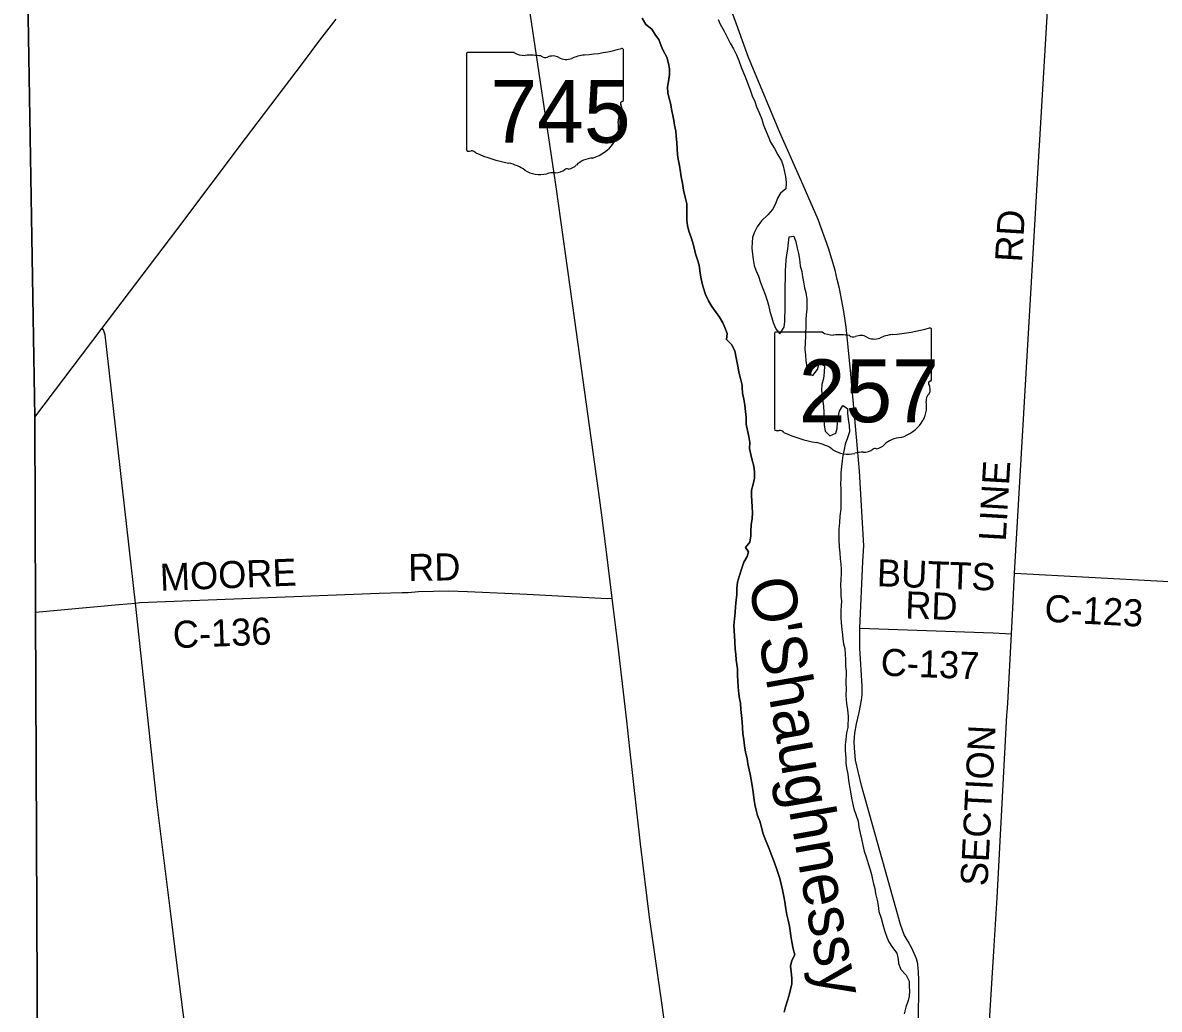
# Model space of a CAD drawing. Extents: x 1674899 to 2057726, y 653888 to 988278.
# Drawn here: x 1780755 to 1793352, y 803604 to 814535 of the extents above; entities that cross this region are included whole.
import ezdxf

# ---------------------------------------------------------------- set-up
doc = ezdxf.new("R2010")
doc.units = 0
for name, color, linetype in [('GM_X_Adjacent_County', 7, 'Continuous'), ('GM_X_County', 7, 'Continuous'), ('GM_X_County_Road', 7, 'Continuous'), ('GM_X_County_Road_Text', 7, 'Continuous'), ('GM_X_Major_Lake', 7, 'Continuous'), ('GM_X_Major_Lake_Text', 7, 'Continuous'), ('GM_X_Major_River', 7, 'Continuous'), ('GM_X_State_Location', 7, 'Continuous'), ('GM_X_State_Route', 7, 'Continuous'), ('GM_X_State_Shield', 7, 'Continuous'), ('GM_X_Township', 7, 'Continuous'), ('GM_X_US_Route', 7, 'Continuous'), ('SH_Data', 7, 'Continuous')]:
    doc.layers.add(name, color=color, linetype=linetype)

msp = doc.modelspace()

# ---------------------------------------------------------------- linework, layer by layer
at = {"layer": 'GM_X_Adjacent_County'}
msp.add_lwpolyline([(1780755, 818148), (1780889, 810163), (1780895, 808002), (1780927, 801312), (1780979, 800357), (1781040, 795733), (1781062, 793102), (1781083, 789921), (1781088, 789265), (1781086, 787507), (1781084, 787075), (1781136, 786470), (1781151, 786236), (1781162, 786094), (1781118, 783904)], dxfattribs=at)
at = {"layer": 'GM_X_County'}
msp.add_lwpolyline([(1781118, 783904), (1781162, 786094), (1781151, 786236), (1781136, 786470), (1781084, 787075), (1781086, 787507), (1781088, 789265), (1781083, 789921), (1781062, 793102), (1781040, 795733), (1780979, 800357), (1780927, 801312), (1780895, 808002), (1780889, 810163), (1780755, 818148)], dxfattribs=at)
at = {"layer": 'GM_X_County_Road'}
for points in [[(1791713, 807764), (1791713, 807764), (1791727, 808049), (1791747, 808435), (1791981, 812422), (1791996, 812680), (1792152, 815352), (1792421, 819851), (1792558, 822011)], [(1782890, 800490), (1782881, 800644), (1782856, 800863), (1782676, 802437), (1782464, 804119), (1782395, 804661), (1782246, 805871), (1782006, 808105), (1781669, 811078), (1781659, 811109), (1781650, 811131), (1781636, 811151)], [(1791747, 808435), (1793395, 808348), (1794980, 808260), (1797031, 808146), (1797107, 808141), (1797153, 808138)], [(1780895, 808002), (1781819, 808088), (1782006, 808105), (1782052, 808109), (1784707, 808216), (1784962, 808220), (1785026, 808223), (1785143, 808231), (1785474, 808240), (1785685, 808234), (1786347, 808204), (1787231, 808155), (1787289, 808159)], [(1790033, 807825), (1791509, 807773), (1791713, 807764)], [(1791328, 800949), (1791359, 801588), (1791381, 801980), (1791400, 802336), (1791517, 804248), (1791555, 804839), (1791576, 805255), (1791663, 806861), (1791666, 806898), (1791673, 806996), (1791713, 807764)]]:
    msp.add_lwpolyline(points, dxfattribs=at)
at = {"layer": 'GM_X_Major_Lake'}
for points in [[(1788122, 812288), (1788116, 812346), (1788114, 812413), (1788117, 812471), (1788117, 812527), (1788097, 812601), (1788080, 812679), (1788066, 812758), (1788052, 812826), (1788044, 812878), (1788035, 812954), (1788021, 813022), (1788013, 813072), (1788009, 813141), (1788006, 813203), (1787998, 813283), (1787992, 813333), (1787980, 813401), (1787971, 813452), (1787959, 813508), (1787951, 813558), (1787935, 813642), (1787921, 813694), (1787904, 813757), (1787900, 813823), (1787914, 813885), (1787925, 813961), (1787925, 814023), (1787913, 814085), (1787893, 814155), (1787854, 814228), (1787832, 814280), (1787804, 814348), (1787770, 814399), (1787726, 814463), (1787662, 814517), (1787620, 814586)], [(1788461, 814570), (1788484, 814520), (1788528, 814443), (1788562, 814375), (1788596, 814309), (1788632, 814244), (1788665, 814178), (1788691, 814116), (1788719, 814043), (1788743, 813979), (1788765, 813927), (1788792, 813857), (1788818, 813790), (1788840, 813724), (1788868, 813664), (1788886, 813602), (1788921, 813529), (1788945, 813467), (1788967, 813401), (1788995, 813329), (1789025, 813260), (1789044, 813210), (1789086, 813140), (1789124, 813073), (1789164, 813003), (1789182, 812951), (1789195, 812897), (1789209, 812830), (1789215, 812764), (1789213, 812696), (1789154, 812646), (1789120, 812590), (1789098, 812528), (1789065, 812464), (1789015, 812406), (1788944, 812339), (1788894, 812275), (1788862, 812207), (1788845, 812155), (1788839, 812104), (1788837, 812038), (1788843, 811972), (1788850, 811912), (1788862, 811846), (1788880, 811794), (1788910, 811727), (1788931, 811657), (1788959, 811591), (1788985, 811523), (1789007, 811456), (1789019, 811404), (1789034, 811334), (1789056, 811266), (1789074, 811213), (1789102, 811143), (1789148, 811087), (1789194, 811161), (1789200, 811223), (1789203, 811273), (1789205, 811339), (1789207, 811409), (1789205, 811471), (1789204, 811526), (1789204, 811590), (1789208, 811726), (1789209, 811790), (1789211, 811840), (1789217, 811908), (1789222, 811960), (1789234, 812031), (1789250, 812163), (1789301, 812169), (1789322, 812106), (1789338, 812038), (1789352, 811978), (1789364, 811916), (1789373, 811843), (1789389, 811777), (1789397, 811721), (1789407, 811663), (1789419, 811599), (1789434, 811544), (1789444, 811472), (1789444, 811362), (1789439, 811300)], [(1788728, 810520), (1788712, 810592), (1788693, 810662), (1788683, 810712), (1788673, 810768), (1788663, 810820), (1788647, 810899), (1788612, 810971), (1788554, 811025), (1788562, 811092), (1788538, 811158), (1788514, 811208), (1788477, 811272), (1788441, 811323), (1788391, 811389), (1788357, 811453), (1788323, 811524), (1788299, 811592), (1788286, 811646), (1788272, 811716), (1788258, 811784), (1788252, 811847), (1788235, 811907), (1788213, 811973), (1788195, 812041), (1788179, 812106), (1788162, 812156), (1788138, 812224), (1788122, 812288)], [(1789439, 811300), (1789435, 811250), (1789433, 811198), (1789432, 811067), (1789428, 810987), (1789424, 810917), (1789429, 810851), (1789435, 810791), (1789441, 810739), (1789453, 810668)], [(1789453, 810668), (1789455, 810652), (1789511, 810626), (1789565, 810692), (1789583, 810764), (1789643, 810734), (1789639, 810662), (1789631, 810591), (1789612, 810527), (1789608, 810459), (1789614, 810407), (1789622, 810339), (1789629, 810287), (1789633, 810215), (1789637, 810150), (1789637, 810080), (1789650, 810008), (1789700, 809956), (1789767, 809988), (1789783, 810038), (1789787, 810106), (1789791, 810166), (1789806, 810232), (1789846, 810294), (1789898, 810260), (1789896, 810209), (1789902, 810141), (1789913, 810073), (1789917, 810003), (1789897, 809935), (1789870, 809865), (1789858, 809807), (1789846, 809739), (1789837, 809681), (1789829, 809616), (1789823, 809548), (1789821, 809482), (1789818, 809428), (1789822, 809362), (1789824, 809300), (1789823, 809200), (1789821, 809147), (1789813, 809067), (1789806, 808997), (1789800, 808925), (1789802, 808875), (1789802, 808809), (1789805, 808725), (1789813, 808662), (1789815, 808596), (1789821, 808534), (1789826, 808482), (1789826, 808426), (1789824, 808374), (1789820, 808304), (1789821, 808235), (1789823, 808181), (1789829, 808131), (1789827, 808075), (1789824, 808023), (1789822, 807941), (1789826, 807889), (1789833, 807812), (1789841, 807754), (1789845, 807704), (1789853, 807652), (1789867, 807602), (1789870, 807534), (1789874, 807482), (1789874, 807409), (1789880, 807347), (1789879, 807213), (1789881, 807159), (1789878, 807079), (1789884, 806993), (1789896, 806920), (1789902, 806850), (1789901, 806726), (1789887, 806666), (1789878, 806594), (1789870, 806532), (1789872, 806469), (1789877, 806387), (1789879, 806331), (1789885, 806279), (1789899, 806209), (1789908, 806141), (1789920, 806072), (1789928, 806014), (1789940, 805944), (1789950, 805892), (1789967, 805824), (1789987, 805762), (1790015, 805689), (1790023, 805621), (1790038, 805553), (1790050, 805493), (1790066, 805420), (1790080, 805356), (1790105, 805292), (1790127, 805220)], [(1789264, 804082), (1789278, 804144), (1789311, 804206), (1789295, 804274), (1789281, 804352), (1789267, 804416), (1789260, 804472), (1789254, 804525), (1789240, 804591), (1789224, 804651), (1789211, 804717), (1789201, 804793), (1789191, 804853), (1789175, 804926), (1789160, 804990), (1789146, 805054), (1789128, 805108), (1789104, 805176), (1789076, 805255), (1789057, 805305), (1789029, 805383), (1789007, 805435), (1788985, 805490), (1788959, 805560), (1788944, 805622), (1788924, 805688), (1788898, 805751), (1788882, 805823), (1788869, 805873), (1788857, 805945), (1788849, 806009), (1788841, 806084), (1788828, 806146), (1788816, 806208), (1788808, 806258), (1788792, 806322), (1788783, 806382), (1788767, 806453), (1788755, 806523), (1788747, 806589), (1788736, 806661), (1788734, 806721), (1788730, 806787), (1788720, 806858), (1788715, 806926), (1788709, 806996), (1788699, 807048), (1788691, 807100), (1788684, 807174), (1788680, 807245), (1788678, 807297), (1788677, 807375), (1788671, 807425), (1788661, 807477), (1788657, 807539), (1788651, 807594), (1788646, 807676), (1788644, 807744), (1788640, 807794), (1788638, 807856), (1788645, 807930), (1788653, 808000), (1788655, 808066), (1788662, 808137), (1788668, 808201), (1788668, 808265), (1788677, 808337), (1788699, 808411), (1788721, 808481), (1788748, 808557), (1788786, 808619), (1788800, 808671), (1788764, 808721), (1788813, 808781), (1788825, 808851), (1788825, 808902), (1788828, 808970), (1788838, 809040), (1788844, 809106), (1788841, 809172), (1788837, 809232), (1788833, 809296), (1788833, 809356), (1788850, 809423), (1788866, 809487), (1788864, 809557), (1788859, 809623), (1788841, 809687), (1788825, 809751), (1788811, 809816), (1788812, 809882), (1788802, 809950), (1788788, 810016), (1788774, 810088), (1788773, 810165), (1788767, 810229), (1788757, 810297), (1788749, 810365), (1788732, 810429), (1788730, 810495), (1788728, 810520)], [(1790127, 805220), (1790149, 805150), (1790161, 805095), (1790172, 805043), (1790184, 804993), (1790198, 804941), (1790206, 804885), (1790226, 804811), (1790235, 804752), (1790245, 804686), (1790269, 804612), (1790289, 804544), (1790306, 804476), (1790332, 804403), (1790354, 804351), (1790396, 804287), (1790442, 804224), (1790457, 804160), (1790463, 804110), (1790489, 804044), (1790547, 803980), (1790579, 803915), (1790578, 803857), (1790582, 803803), (1790580, 803749), (1790568, 803699), (1790543, 803625), (1790525, 803553)], [(1789193, 803573), (1789210, 803629), (1789230, 803701), (1789253, 803773), (1789265, 803823), (1789281, 803885), (1789279, 803947), (1789272, 804018), (1789264, 804082)]]:
    msp.add_lwpolyline(points, dxfattribs=at)
at = {"layer": 'GM_X_Major_River'}
for points in [[(1787620, 814586), (1787662, 814517), (1787726, 814463), (1787770, 814399), (1787804, 814348), (1787832, 814280), (1787854, 814228), (1787893, 814155), (1787913, 814085), (1787925, 814023), (1787925, 813961), (1787914, 813885), (1787900, 813823), (1787904, 813757), (1787921, 813694), (1787935, 813642), (1787951, 813558), (1787959, 813508), (1787971, 813452), (1787980, 813401), (1787992, 813333), (1787998, 813283), (1788006, 813203), (1788009, 813141), (1788013, 813072), (1788021, 813022), (1788035, 812954), (1788044, 812878), (1788052, 812826), (1788066, 812758), (1788080, 812679), (1788097, 812601), (1788117, 812527), (1788117, 812471), (1788114, 812413), (1788116, 812346), (1788122, 812288)], [(1788461, 814570), (1788484, 814520), (1788528, 814443), (1788562, 814375), (1788596, 814309), (1788632, 814244), (1788665, 814178), (1788691, 814116), (1788719, 814043), (1788743, 813979), (1788765, 813927), (1788792, 813857), (1788818, 813790), (1788840, 813724), (1788868, 813664), (1788886, 813602), (1788921, 813529), (1788945, 813467), (1788967, 813401), (1788995, 813329), (1789025, 813260), (1789044, 813210), (1789086, 813140), (1789124, 813073), (1789164, 813003), (1789182, 812951), (1789195, 812897), (1789209, 812830), (1789215, 812764), (1789213, 812696), (1789154, 812646), (1789120, 812590), (1789098, 812528), (1789065, 812464), (1789015, 812406), (1788944, 812339), (1788894, 812275), (1788862, 812207), (1788845, 812155), (1788839, 812104), (1788837, 812038), (1788843, 811972), (1788850, 811912), (1788862, 811846), (1788880, 811794), (1788910, 811727), (1788931, 811657), (1788959, 811591), (1788985, 811523), (1789007, 811456), (1789019, 811404), (1789034, 811334), (1789056, 811266), (1789074, 811213), (1789102, 811143), (1789148, 811087), (1789194, 811161), (1789200, 811223), (1789203, 811273), (1789205, 811339), (1789207, 811409), (1789205, 811471), (1789204, 811526), (1789204, 811590), (1789208, 811726), (1789209, 811790), (1789211, 811840), (1789217, 811908), (1789222, 811960), (1789234, 812031), (1789250, 812163), (1789301, 812169), (1789322, 812106), (1789338, 812038), (1789352, 811978), (1789364, 811916), (1789373, 811843), (1789389, 811777), (1789397, 811721), (1789407, 811663), (1789419, 811599), (1789434, 811544), (1789444, 811472), (1789444, 811362), (1789439, 811300)], [(1788122, 812288), (1788138, 812224), (1788162, 812156), (1788179, 812106), (1788195, 812041), (1788213, 811973), (1788235, 811907), (1788252, 811847), (1788258, 811784), (1788272, 811716), (1788286, 811646), (1788299, 811592), (1788323, 811524), (1788357, 811453), (1788391, 811389), (1788441, 811323), (1788477, 811272), (1788514, 811208), (1788538, 811158), (1788562, 811092), (1788554, 811025), (1788612, 810971), (1788647, 810899), (1788663, 810820), (1788673, 810768), (1788683, 810712), (1788693, 810662), (1788712, 810592), (1788728, 810520)], [(1789439, 811300), (1789435, 811250), (1789433, 811198), (1789432, 811067), (1789428, 810987), (1789424, 810917), (1789429, 810851), (1789435, 810791), (1789441, 810739), (1789453, 810668)], [(1789453, 810668), (1789455, 810652), (1789511, 810626), (1789565, 810692), (1789583, 810764), (1789643, 810734), (1789639, 810662), (1789631, 810591), (1789612, 810527), (1789608, 810459), (1789614, 810407), (1789622, 810339), (1789629, 810287), (1789633, 810215), (1789637, 810150), (1789637, 810080), (1789650, 810008), (1789700, 809956), (1789767, 809988), (1789783, 810038), (1789787, 810106), (1789791, 810166), (1789806, 810232), (1789846, 810294), (1789898, 810260), (1789896, 810209), (1789902, 810141), (1789913, 810073), (1789917, 810003), (1789897, 809935), (1789870, 809865), (1789858, 809807), (1789846, 809739), (1789837, 809681), (1789829, 809616), (1789823, 809548), (1789821, 809482), (1789818, 809428), (1789822, 809362), (1789824, 809300), (1789823, 809200), (1789821, 809147), (1789813, 809067), (1789806, 808997), (1789800, 808925), (1789802, 808875), (1789802, 808809), (1789805, 808725), (1789813, 808662), (1789815, 808596), (1789821, 808534), (1789826, 808482), (1789826, 808426), (1789824, 808374), (1789820, 808304), (1789821, 808235), (1789823, 808181), (1789829, 808131), (1789827, 808075), (1789824, 808023), (1789822, 807941), (1789826, 807889), (1789833, 807812), (1789841, 807754), (1789845, 807704), (1789853, 807652), (1789867, 807602), (1789870, 807534), (1789874, 807482), (1789874, 807409), (1789880, 807347), (1789879, 807213), (1789881, 807159), (1789878, 807079), (1789884, 806993), (1789896, 806920), (1789902, 806850), (1789901, 806726), (1789887, 806666), (1789878, 806594), (1789870, 806532), (1789872, 806469), (1789877, 806387), (1789879, 806331), (1789885, 806279), (1789899, 806209), (1789908, 806141), (1789920, 806072), (1789928, 806014), (1789940, 805944), (1789950, 805892), (1789967, 805824), (1789987, 805762), (1790015, 805689), (1790023, 805621), (1790038, 805553), (1790050, 805493), (1790066, 805420), (1790080, 805356), (1790105, 805292), (1790127, 805220)], [(1788728, 810520), (1788730, 810495), (1788732, 810429), (1788749, 810365), (1788757, 810297), (1788767, 810229), (1788773, 810165), (1788774, 810088), (1788788, 810016), (1788802, 809950), (1788812, 809882), (1788811, 809816), (1788825, 809751), (1788841, 809687), (1788859, 809623), (1788864, 809557), (1788866, 809487), (1788850, 809423), (1788833, 809356), (1788833, 809296), (1788837, 809232), (1788841, 809172), (1788844, 809106), (1788838, 809040), (1788828, 808970), (1788825, 808902), (1788825, 808851), (1788813, 808781), (1788764, 808721), (1788800, 808671), (1788786, 808619), (1788748, 808557), (1788721, 808481), (1788699, 808411), (1788677, 808337), (1788668, 808265), (1788668, 808201), (1788662, 808137), (1788655, 808066), (1788653, 808000), (1788645, 807930), (1788638, 807856), (1788640, 807794), (1788644, 807744), (1788646, 807676), (1788651, 807594), (1788657, 807539), (1788661, 807477), (1788671, 807425), (1788677, 807375), (1788678, 807297), (1788680, 807245), (1788684, 807174), (1788691, 807100), (1788699, 807048), (1788709, 806996), (1788715, 806926), (1788720, 806858), (1788730, 806787), (1788734, 806721), (1788736, 806661), (1788747, 806589), (1788755, 806523), (1788767, 806453), (1788783, 806382), (1788792, 806322), (1788808, 806258), (1788816, 806208), (1788828, 806146), (1788841, 806084), (1788849, 806009), (1788857, 805945), (1788869, 805873), (1788882, 805823), (1788898, 805751), (1788924, 805688), (1788944, 805622), (1788959, 805560), (1788985, 805490), (1789007, 805435), (1789029, 805383), (1789057, 805305), (1789076, 805255), (1789104, 805176), (1789128, 805108), (1789146, 805054), (1789160, 804990), (1789175, 804926), (1789191, 804853), (1789201, 804793), (1789211, 804717), (1789224, 804651), (1789240, 804591), (1789254, 804525), (1789260, 804472), (1789267, 804416), (1789281, 804352), (1789295, 804274), (1789311, 804206), (1789278, 804144), (1789264, 804082)], [(1790127, 805220), (1790149, 805150), (1790161, 805095), (1790172, 805043), (1790184, 804993), (1790198, 804941), (1790206, 804885), (1790226, 804811), (1790235, 804752), (1790245, 804686), (1790269, 804612), (1790289, 804544), (1790306, 804476), (1790332, 804403), (1790354, 804351), (1790396, 804287), (1790442, 804224), (1790457, 804160), (1790463, 804110), (1790489, 804044), (1790547, 803980), (1790579, 803915), (1790578, 803857), (1790582, 803803), (1790580, 803749), (1790568, 803699), (1790543, 803625), (1790525, 803553)], [(1789264, 804082), (1789272, 804018), (1789279, 803947), (1789281, 803885), (1789265, 803823), (1789253, 803773), (1789230, 803701), (1789210, 803629), (1789193, 803573)]]:
    msp.add_lwpolyline(points, dxfattribs=at)
at = {"layer": 'GM_X_State_Route'}
for points in [[(1789933, 810648), (1789882, 811163), (1789857, 811335), (1789809, 811591), (1789782, 811691), (1789760, 811794), (1789687, 812036), (1789570, 812353), (1789380, 812793), (1789145, 813319), (1788800, 814150), (1788666, 814519), (1788535, 814873)], [(1787872, 803431), (1787846, 803622), (1787700, 804624), (1787601, 805437), (1787484, 806491), (1787451, 806800), (1787357, 807594), (1787289, 808159), (1787220, 808700), (1787174, 809078), (1787137, 809350), (1786980, 810466), (1786873, 811238), (1786667, 812717), (1786361, 814768)], [(1789995, 809943), (1789934, 810642), (1789933, 810648)], [(1790677, 804093), (1790675, 804108), (1790660, 804164), (1790640, 804215), (1790609, 804281), (1790568, 804355), (1790526, 804429), (1790485, 804541), (1790432, 804726), (1790051, 806083), (1789985, 806362), (1789973, 806499), (1789971, 806567), (1789977, 806663), (1789996, 806768), (1790026, 806892), (1790053, 807030), (1790058, 807087), (1790058, 807184), (1790033, 807604), (1790033, 807825), (1790068, 808566), (1790079, 808738), (1790028, 809565), (1789995, 809943)], [(1790684, 803416), (1790687, 803933), (1790683, 804011), (1790681, 804061), (1790677, 804093)]]:
    msp.add_lwpolyline(points, dxfattribs=at)
at = {"layer": 'GM_X_State_Shield'}
for p, q in [((1785673, 814188), (1785673, 813131)), ((1786200, 814206), (1785690, 814206)), ((1787413, 813679), (1787413, 814232)), ((1787413, 813680), (1787413, 813679)), ((1789088, 811090), (1789088, 810034)), ((1789614, 811108), (1789105, 811108)), ((1790828, 810582), (1790828, 811135)), ((1790828, 810582), (1790828, 810582))]:
    msp.add_line(p, q, dxfattribs=at)
for centre, major_axis, start_param, end_param in [((1785693, 814190), (20.2, 0), 1.712693, 3.28349), ((1786321, 814329), (196, 0), 4.042523, 4.731795), ((1786386, 813613), (702, 0), 1.404758, 1.657858), ((1786546, 814195), (56.4, 0), 3.836095, 5.185415), ((1786628, 814073), (117, 0), 0.950623, 2.079405), ((1787029, 813883), (371, 0), 1.699011, 2.107814), ((1786794, 815646), (1845, 0), 4.814394, 5.042369), ((1787394, 814234), (19.4, 0), 6.141152, 7.989035), ((1786780, 814241), (141, 0), 4.081561, 5.145723), ((1787409, 813639), (30, 0), 1.883978, 3.671073), ((1787393, 813677), (20.7, 0), 5.05454, 6.418171), ((1787218, 813569), (180, 0), 5.934695, 6.695948), ((1786897, 813378), (462, 0), 5.101752, 6.440018), ((1787483, 813448), (131, 0), 2.387724, 3.262537), ((1785693, 813129), (20.3, 0), 3.00124, 4.508301), ((1785696, 813237), (155, 0), 4.665946, 4.897461), ((1785728, 813070), (56, 0), 0.519207, 1.627899), ((1786435, 814020), (1333, 0), 4.195997, 4.488961), ((1787092, 812834), (253, 0), 1.647645, 2.488434), ((1786038, 812656), (417, 0), 0.823519, 1.323587), ((1786488, 813065), (265, 0), 4.026481, 4.996735), ((1786661, 812986), (141, 0), 4.691044, 5.507374), ((1786788, 812883), (39.7, 0), 1.147584, 2.315152), ((1786771, 813029), (149, 0), 4.937069, 5.64225), ((1786641, 812700), (217, 0), 1.495662, 1.94098), ((1790208, 812549), (1845, 0), 4.814394, 5.042369), ((1790809, 811137), (19.4, 0), 6.141152, 7.989035), ((1789108, 811092), (20.2, 0), 1.712693, 3.28349), ((1789736, 811231), (196, 0), 4.042523, 4.731795), ((1789801, 810515), (702, 0), 1.404758, 1.657858), ((1789960, 811098), (56.4, 0), 3.836095, 5.185415), ((1790043, 810976), (117, 0), 0.950623, 2.079405), ((1790194, 811143), (141, 0), 4.081561, 5.145723), ((1790443, 810786), (371, 0), 1.699011, 2.107814), ((1790823, 810541), (30, 0), 1.883978, 3.671073), ((1790633, 810471), (180, 0), 5.934695, 6.695948), ((1790807, 810580), (20.7, 0), 5.05454, 6.418171), ((1790897, 810350), (131, 0), 2.387724, 3.262537), ((1790311, 810280), (462, 0), 5.101752, 6.440018), ((1789108, 810031), (20.3, 0), 3.00124, 4.508301), ((1789111, 810139), (155, 0), 4.665946, 4.897461), ((1789143, 809973), (56, 0), 0.519207, 1.627899), ((1789849, 810922), (1333, 0), 4.195997, 4.488961), ((1789452, 809559), (417, 0), 0.823519, 1.323587), ((1790506, 809737), (253, 0), 1.647645, 2.488434), ((1789903, 809967), (265, 0), 4.026481, 4.996735), ((1790056, 809602), (217, 0), 1.495662, 1.94098), ((1790075, 809888), (141, 0), 4.691044, 5.507374), ((1790203, 809786), (39.7, 0), 1.147584, 2.315152), ((1790186, 809931), (149, 0), 4.937069, 5.64225)]:
    msp.add_ellipse(centre, major_axis=major_axis, ratio=0.8, start_param=start_param, end_param=end_param, dxfattribs=at)
at = {"layer": 'GM_X_Township'}
msp.add_lwpolyline([(1781118, 783904), (1781162, 786094), (1781151, 786236), (1781136, 786470), (1781084, 787075), (1781086, 787507), (1781088, 789265), (1781083, 789921), (1781062, 793102), (1781040, 795733), (1780979, 800357), (1780927, 801312), (1780895, 808002), (1780889, 810163), (1780755, 818148)], dxfattribs=at)
at = {"layer": 'GM_X_US_Route'}
msp.add_lwpolyline([(1780889, 810163), (1781636, 811151), (1782464, 812239), (1783225, 813253), (1783854, 814085), (1784048, 814342), (1784229, 814573)], dxfattribs=at)
at = {"layer": 'SH_Data'}
msp.add_lwpolyline([(1780889, 810163), (1781636, 811151), (1782464, 812239), (1783225, 813253), (1783854, 814085), (1784048, 814342), (1784229, 814573)], dxfattribs=at)

# ---------------------------------------------------------------- texts
at = {"layer": 'GM_X_County_Road_Text'}
for s, rotation, p in [('RD', 86.5467, (1791830, 811876)), ('LINE', 86.6866, (1791650, 808783)), ('RD', 0.9853, (1785029, 808348)), ('MOORE', 2.2825, (1782281, 808239)), ('BUTTS', 357.8311, (1790218, 808292)), ('RD', 358.0243, (1790532, 807935)), ('C-123', 356.9734, (1792074, 807899)), ('C-136', 2.2024, (1782424, 807604)), ('C-137', 357.7976, (1790260, 807301)), ('SECTION', 87.0738, (1791447, 804963))]:
    msp.add_text(s, height=300, rotation=rotation, dxfattribs=at).set_placement(p)
at = {"layer": 'GM_X_Major_Lake_Text'}
msp.add_text("O'Shaughnessy", height=499.85, rotation=280.0075, dxfattribs=at).set_placement((1788799, 808349))
at = {"layer": 'GM_X_State_Location'}
for s, p in [('s', (1786524, 813589)), ('r', (1786524, 813589)), ('s', (1789938, 810492)), ('r', (1789938, 810492))]:
    msp.add_text(s, height=1, dxfattribs=at).set_placement(p)
for s, p in [('745', (1786171, 813516)), ('257', (1789585, 810419))]:
    msp.add_text(s, height=1, rotation=0, dxfattribs=at).set_placement(p)
at = {"layer": 'GM_X_State_Shield'}
for s, p in [('745', (1785939, 813206)), ('257', (1789356, 810108))]:
    msp.add_text(s, height=696.1, dxfattribs=at).set_placement(p)

doc.saveas('drawing.dxf')
